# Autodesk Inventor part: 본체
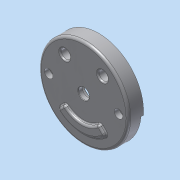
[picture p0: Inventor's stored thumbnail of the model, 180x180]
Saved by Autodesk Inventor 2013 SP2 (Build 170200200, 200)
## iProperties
Created: 2015-04
Part Number: 본체
Material: 알루미늄 6061
Document SubType Name: Modeling
Designer: dgall
Density: 2.71 g/cm^3
Mass: 1043.05 g
Surface Area: 1027.84 cm^2
Volume: 384.89 cm^3
Author: dgall
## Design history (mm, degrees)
sketch "스케치1"
  geometry: L1 (0, 0)-(-94.638, -8.28); L2 (95, 0)-(-95, 0); L3 (0, 0)-(94.638, -8.28); A1 r 95 centre (0, 0) between (-94.638, -8.28) and (-95, 0); 1 further point
  constraints: 6 end point, 4 point on circle, 1 centre point, 1 coincident, 1 horizontal, 1 midpoint
  dimensions: "d1" = 190 diameter of A1; "d5" = 5 deg angle of L2 L1; "d7" = 5 deg angle of L2 L3
extrude "돌출1" new body sketch "스케치1" distance "d3" = 32; taper "d4" = 0 deg
extrude "돌출2" cut sketch "스케치1" distance "d9" = 5; taper "d10" = 0 deg
sketch "스케치2"
  geometry: C1 r 90 at (0, 0); C2 r 15 at (40, -52); C3 r 10 at (40, -52); C4 r 10 at (-40, -52); C5 r 15 at (-40, -52); C6 r 5.5 at (74, 0); C7 r 5.5 at (-74, 0); A1 r 95 centre (0, 0) between (-94.638, 8.28) and (94.638, 8.28) reference; A2 r 95 centre (0, 0) between (94.638, 8.28) and (-94.638, 8.28) reference; 1 further point
  constraints: 7 centre point, 3 equal radius, 3 horizontal alignment, 2 coincident
  dimensions: "d16" = 180 diameter of C1; "d18" = 30 diameter of C2; "d19" = 20 diameter of C3; "d20" = 52 vertical distance of C4.centre point (0, 0); "d21" = 40 horizontal distance of point (0, 0) C2.centre; "d22" = 40 horizontal distance of C4.centre point (0, 0); "d25" = 11 diameter of C6; "d26" = 74 distance of point (0, 0) C6.centre; "d27" = 74 distance of A1.centre C7.centre
extrude "돌출3" cut sketch "스케치2" distance "d28" = 18; taper "d29" = 0 deg
sketch "스케치3"
  geometry: C1 r 90 at (0, 0) reference; C2 r 35 at (0, 0)
  constraints: 1 centre point, 1 coincident
  dimensions: "d30" = 70 diameter of C2
extrude "돌출4" join sketch "스케치3" distance "d33" = 10; taper "d34" = -10 deg
sketch "스케치4"
  geometry: C1 r 33.237 at (0, 0) reference; C2 r 25 at (0, 0); C3 r 11.5 at (0, 0)
  constraints: 2 centre point, 2 coincident
  dimensions: "d35" = 50 diameter of C2; "d37" = 23 diameter of C3
extrude "돌출5" cut sketch "스케치4" distance "d38" = 15; taper "d39" = 0 deg
extrude "돌출6" cut sketch "스케치4" stored distance "d40" = 15; taper "d41" = 0 deg
sketch "스케치5"
  geometry: L1 (76.916, -12)-(47.117, -12); L2 (-47.117, -12)-(-76.916, -12); C1 r 15 at (40, -52) reference; C2 r 15 at (-40, -52) reference; A1 r 10 centre (47.117, -22) between (47.117, -12) and (38.056, -17.769); A2 r 42 centre (0, 0) between (-38.056, -17.769) and (38.056, -17.769); A3 r 10 centre (-47.117, -22) between (-38.056, -17.769) and (-47.117, -12); A4 r 10 centre (-76.916, -22) between (-76.916, -12) and (-86.53, -24.75); A5 r 10 centre (76.916, -22) between (86.53, -24.75) and (76.916, -12); A6 r 90 centre (0, 0) between (-89.658, 7.844) and (89.658, 7.844) reference; A7 r 90 centre (0, 0) between (-86.53, -24.75) and (86.53, -24.75); 1 further point
  constraints: 12 point on circle, 7 tangent, 6 centre point, 4 end point, 4 equal radius, 2 collinear, 2 concentric, 1 horizontal
  dimensions: "d48" = 84 diameter of A2; "d49" = 10 radius of A5; "d50" = 12 distance from line of point (0, 0) L1; "d51" = 12 distance from line of L2 point (0, 0)
extrude "돌출7" cut sketch "스케치5" distance "d52" = 25; taper "d53" = 0 deg
sketch "스케치6"
  geometry: A1 r 90 centre (0, 0) between (86.53, -24.75) and (-86.53, -24.75) reference; A2 r 59 centre (0, 19) between (58.704, 13.1) and (-58.704, 13.1); A3 r 41 centre (0, 19) between (40.794, 14.9) and (-40.794, 14.9); A4 r 9 centre (49.749, 14) between (40.794, 14.9) and (58.704, 13.1); A5 r 9 centre (-49.749, 14) between (-58.704, 13.1) and (-40.794, 14.9)
  constraints: 8 point on circle, 4 centre point, 1 equal radius, 1 horizontal alignment, 1 vertical alignment
  dimensions: "d59" = 19 distance of A2.centre A1.centre; "d60" = 59 radius of A2; "d61" = 41 radius of A3; "d62" = 5 vertical distance of A4.centre A2.centre; "d63" = 9 radius of A4
extrude "돌출8" cut sketch "스케치6" distance "d64" = 7; taper "d65" = 0 deg
fillet "모깎기1" dims "d66" = 1
sketch "스케치7"
  geometry: C1 r 5.5 at (0, 0) reference; C2 r 9 at (0, 0); C3 r 5.5 at (-148, 0) reference; C4 r 9 at (-148, 0); 1 further point
  constraints: 2 centre point, 2 coincident
  dimensions: "d69" = 18 diameter of C2; "d70" = 18 diameter of C4
extrude "돌출9" join sketch "스케치7" stored distance "d71" = 7; taper "d72" = 0 deg
extrude "돌출10" cut sketch "스케치7" stored distance "d73" = 7; taper "d74" = 0 deg
sketch "스케치8"
  geometry: C1 r 5.5 at (74, 0) reference; C2 r 5.5 at (-74, 0) reference; C3 r 9 at (-74, 0); C4 r 9 at (74, 0)
  constraints: 2 centre point, 2 coincident
  dimensions: "d75" = 18 diameter of C3; "d77" = 18 diameter of C4
extrude "돌출11" cut sketch "스케치8" distance "d78" = 11; taper "d79" = 0 deg
extrude "돌출12" cut sketch "스케치2" stored distance "d80" = 11; taper "d81" = 0 deg
sketch "스케치9"
  geometry: L1 (0, -15)-(6, -15); L2 (6, -15)-(6, 15); L3 (6, 15)-(0, 15); L4 (0, -15)-(0, 15); L5 (-95, 0)-(-95, -6); L6 (-95, -6)-(-65, -6); L7 (-65, -6)-(-65, 0); L8 (-95, 0)-(-94.478, 0); L9 (-65, 0)-(-95, 0); C1 r 10 at (-80, 0) reference; A1 r 15 centre (0, 0) between (0, -15) and (0, 15) reference; A2 r 15 centre (-80, 0) between (-95, 0) and (-65, 0) reference; 1 further point
  constraints: 18 end point, 4 perpendicular, 4 point on circle, 4 tangent, 1 collinear, 1 horizontal, 1 parallel
  dimensions: "d82" = 6 distance between parallel lines of L2 L4; "d86" = 6 distance between parallel lines of L9 L6
extrude "돌출13" cut sketch "스케치9" distance "d84" = 3; taper "d85" = 0 deg
extrude "돌출14" cut sketch "스케치9" distance "d87" = 3; taper "d88" = 0 deg
chamfer "모따기1" distance "d89" = 1; stored, may be unused: second distance "d90" = 2, angle "d91" = 45 deg
chamfer "모따기2" distance "d92" = 1; stored, may be unused: second distance "d93" = 2, angle "d94" = 45 deg
fillet "모깎기2" dims "d95" = 3
fillet "모깎기3" dims "d96" = 5
fillet "모깎기4" dims "d97" = 3
chamfer "모따기3" distance "d98" = 1; stored, may be unused: second distance "d99" = 2, angle "d100" = 45 deg
sketch "스케치10"
  geometry: L1 (-50.912, -50.912)-(0, 0); L2 (50.912, -50.912)-(0, 0); L3 (0, 0)-(-74, 0); C1 r 90 at (0, 0) reference; C2 r 9 at (-74, 0) reference; A1 r 72 centre (0, 0) between (-50.912, -50.912) and (50.912, -50.912); A2 r 51 centre (0, 0) between (-36.062, -36.062) and (36.062, -36.062)
  constraints: 6 end point, 4 point on circle, 2 centre point, 2 coincident, 2 point on line, 1 horizontal
  dimensions: "d105" = 72 radius of A1; "d107" = 51 radius of A2; "d110" = 45 deg angle of L3 L1; "d111" = 45 deg angle of L3 L2
extrude "돌출15" join sketch "스케치10" distance "d112" = 5; taper "d113" = 0 deg
fillet "모깎기5" dims "d114" = 5
fillet "모깎기6" dims "d115" = 3
fillet "모깎기7" dims "d116" = 5
fillet "모깎기8" dims "d117" = 3
fillet "모깎기9" dims "d118" = 3
fillet "모깎기10" dims "d119" = 3
fillet "모깎기11" dims "d120" = 0.3
node "솔리드1"
mirror "대칭1"
mirror "대칭2"
